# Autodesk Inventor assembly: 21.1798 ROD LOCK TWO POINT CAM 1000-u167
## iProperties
Created: 2007-03
Part Number: 21.1798 ROD LOCK TWO POINT CAM 1000-u167
Document SubType Name: Assembly
Designer: Andy Moles
Translation Standard: STEP AP203
File Name: 1000-U167_ASM
Preprocessor: PRO/ENGINEER BY PARAMETRIC TECHNOLOGY CORPORATION, 2001390
Postprocessor: Build: 344b, Release: 11 SP2 - Date: Fri 08/18/2006
Sent Units: MILLIMETERS
Uncertainty: 0.005452955411917
Author: Andy Moles
